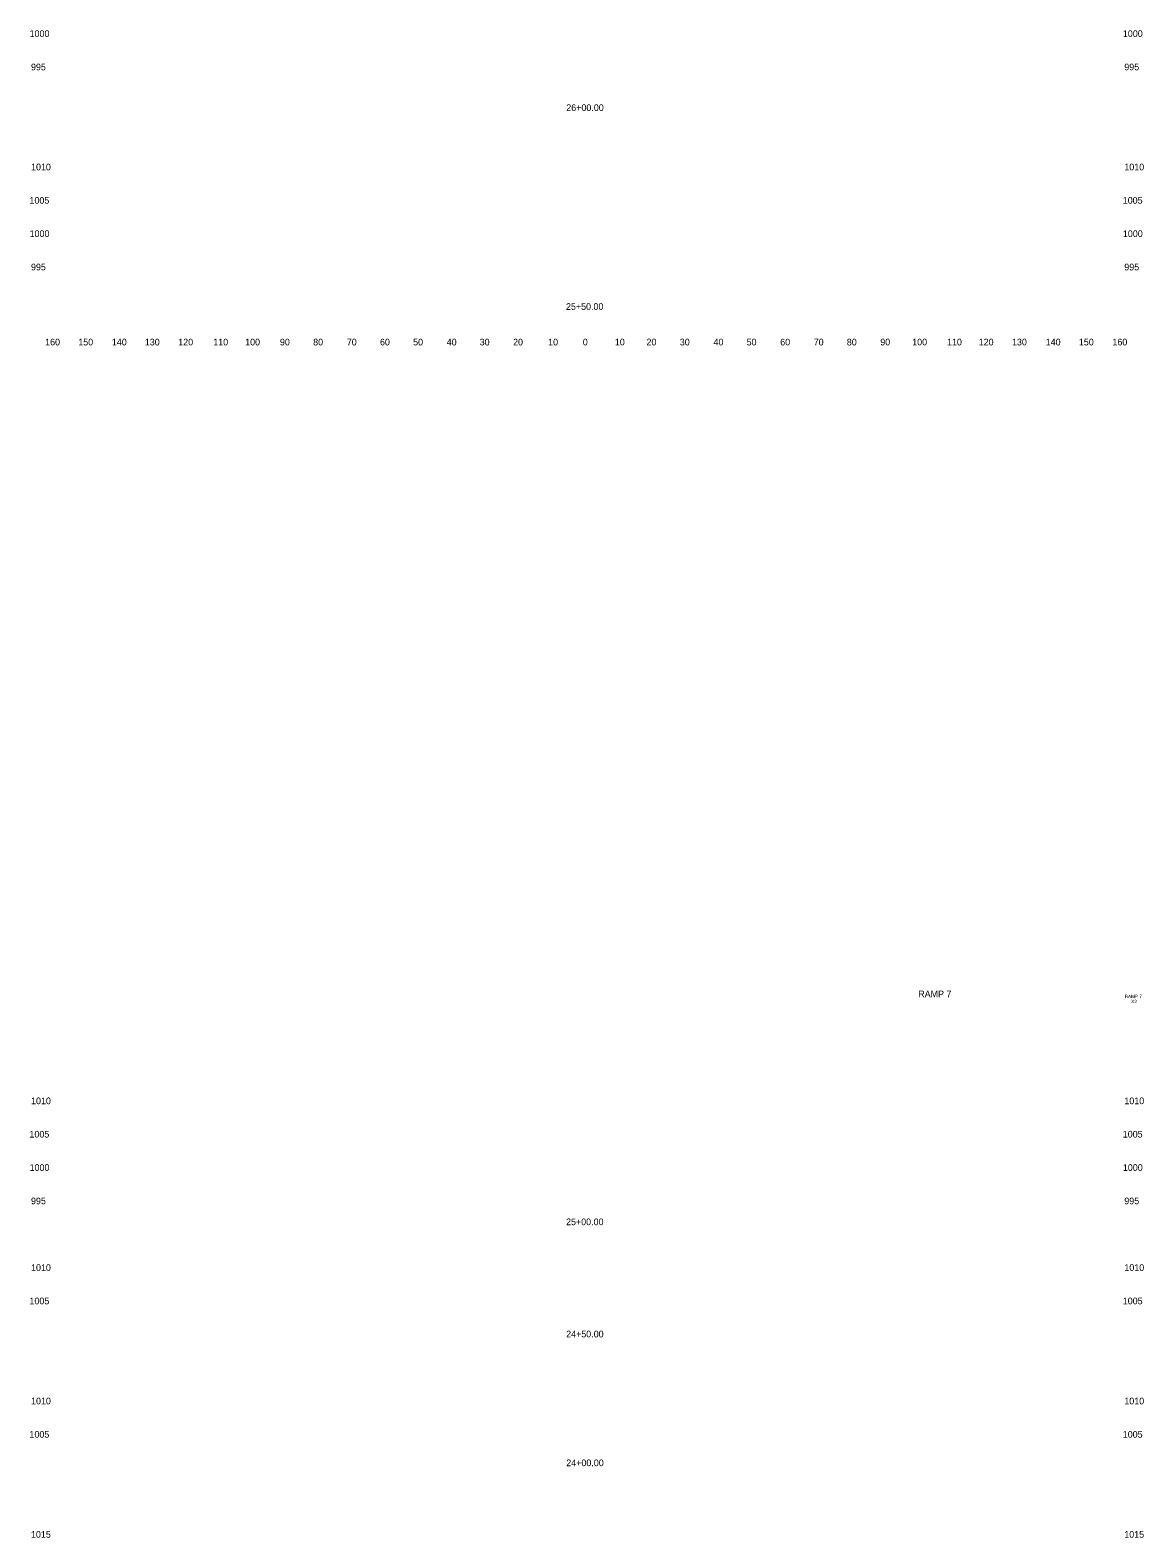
# Model space of a CAD drawing. Extents: x 4994 to 5701, y 4992 to 6804.
# Drawn here: x 4993.6 to 5327.5, y 5440 to 5892 of the extents above; entities that cross this region are included whole.
import ezdxf

# ---------------------------------------------------------------- set-up
doc = ezdxf.new("R2010")
doc.units = 0
for name, color, linetype in [('CLS_Search_Dist', 7, 'Continuous'), ('RD_XE_Ground', 7, 'Continuous'), ('UC_PD_Text', 7, 'Continuous')]:
    doc.layers.add(name, color=color, linetype=linetype)

msp = doc.modelspace()

# ---------------------------------------------------------------- texts
at = {"layer": 'CLS_Search_Dist'}
for s, p in [('1000', (4993.44, 5890)), ('1000', (5321.24, 5890)), ('995', (4993.86, 5880)), ('995', (5321.66, 5880)), ('1010', (4993.88, 5850)), ('1010', (5321.68, 5850)), ('1005', (4993.4, 5840)), ('1005', (5321.2, 5840)), ('1000', (4993.44, 5830)), ('1000', (5321.24, 5830)), ('995', (4993.86, 5820)), ('995', (5321.66, 5820)), ('160', (4998.1, 5797.5)), ('150', (5008.04, 5797.5)), ('140', (5018.1, 5797.5)), ('130', (5027.99, 5797.5)), ('120', (5038.01, 5797.5)), ('110', (5048.51, 5797.5)), ('100', (5058.07, 5797.5)), ('90', (5068.5, 5797.5)), ('80', (5078.46, 5797.5)), ('70', (5088.54, 5797.5)), ('60', (5098.5, 5797.5)), ('50', (5108.43, 5797.5)), ('40', (5118.5, 5797.5)), ('30', (5128.39, 5797.5)), ('20', (5138.4, 5797.5)), ('10', (5148.91, 5797.5)), ('0', (5159.3, 5797.5)), ('0', (5159.3, 5797.5)), ('10', (5168.91, 5797.5)), ('20', (5178.4, 5797.5)), ('30', (5188.39, 5797.5)), ('40', (5198.5, 5797.5)), ('50', (5208.43, 5797.5)), ('60', (5218.5, 5797.5)), ('70', (5228.54, 5797.5)), ('80', (5238.46, 5797.5)), ('90', (5248.5, 5797.5)), ('100', (5258.07, 5797.5)), ('110', (5268.51, 5797.5)), ('120', (5278.01, 5797.5)), ('130', (5287.99, 5797.5)), ('140', (5298.1, 5797.5)), ('150', (5308.04, 5797.5)), ('160', (5318.1, 5797.5)), ('1010', (4993.88, 5570)), ('1010', (5321.68, 5570)), ('1005', (4993.4, 5560)), ('1005', (5321.2, 5560)), ('1000', (4993.44, 5550)), ('1000', (5321.24, 5550)), ('995', (4993.86, 5540)), ('995', (5321.66, 5540)), ('1010', (4993.88, 5520)), ('1010', (5321.68, 5520)), ('1005', (4993.4, 5510)), ('1005', (5321.2, 5510)), ('1010', (4993.88, 5480)), ('1010', (5321.68, 5480)), ('1005', (4993.4, 5470)), ('1005', (5321.2, 5470)), ('1015', (4993.85, 5440)), ('1015', (5321.65, 5440))]:
    msp.add_text(s, height=2, dxfattribs=at).set_placement(p)
at = {"layer": 'RD_XE_Ground'}
for s, p in [('26+00.00', (5154.35, 5867.78)), ('25+50.00', (5154.26, 5808.16)), ('25+00.00', (5154.29, 5533.72)), ('24+50.00', (5154.32, 5500.08)), ('24+00.00', (5154.35, 5461.46))]:
    msp.add_text(s, height=2, dxfattribs=at).set_placement(p)
at = {"layer": 'UC_PD_Text'}
for s, height, p in [('RAMP 7', 2, (5259.88, 5602.06)), ('RAMP 7', 1, (5321.78, 5601.8)), ('X2', 1, (5323.74, 5600.3))]:
    msp.add_text(s, height=height, dxfattribs=at).set_placement(p)

doc.saveas('drawing.dxf')
